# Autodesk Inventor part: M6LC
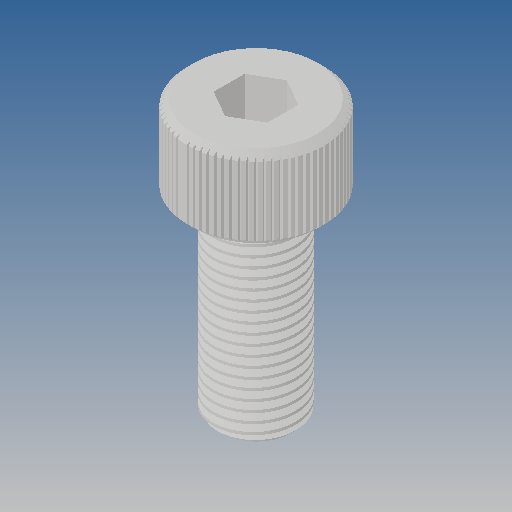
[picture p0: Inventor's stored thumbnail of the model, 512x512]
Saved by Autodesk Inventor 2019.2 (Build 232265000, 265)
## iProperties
Created: 2010-02
Part Number: M6LC
Material: Ogólny
Document SubType Name: Modeling
Designer: CADENGINEERING4
Density: 1 g/cm^3
Appearance: Domyślna
Author: CADENGINEERING4
Revision Number: 1LAST_VERSION
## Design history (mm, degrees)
feature "Baza1"
node "Bryła1"
